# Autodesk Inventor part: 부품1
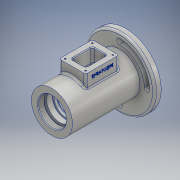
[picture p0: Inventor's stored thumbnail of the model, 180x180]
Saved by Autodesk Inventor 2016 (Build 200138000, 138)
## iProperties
Created: 2017-05
Part Number: 부품1
Material: 알루미늄 6061
Document SubType Name: Modeling
Designer: USER
Density: 2.7 g/cm^3
Appearance: 알루미늄 - 평지
Mass: 676.85 g
Surface Area: 618.164 cm^2
Volume: 250.685 cm^3
Author: USER
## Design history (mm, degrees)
sketch "스케치2"
  geometry: C1 r 53 at (0, 0); 1 further point
  constraints: 1 centre point, 1 coincident
  dimensions: "d0" = 106 diameter of C1
extrude "돌출1" new body sketch "스케치2" distance "d1" = 10; taper "d2" = 0 deg
sketch "스케치3"
  geometry: A1 r 41.5 centre (0, 0) between (0, 41.5) and (-41.5, 0); A2 r 4 centre (0, 41.5) between (0, 37.5) and (0, 45.5); A3 r 4 centre (-41.5, 0) between (-45.5, 0) and (-37.5, 0); A4 r 4 centre (41.5, 0) between (45.5, 0) and (37.5, 0); A5 r 4 centre (0, -41.5) between (0, -37.5) and (0, -45.5); A6 r 37.5 centre (0, 0) between (0, 37.5) and (-37.5, 0); A7 r 37.5 centre (0, 0) between (0, -37.5) and (37.5, 0); A8 r 45.5 centre (0, 0) between (0, 45.5) and (-45.5, 0); A9 r 45.5 centre (0, 0) between (0, -45.5) and (45.5, 0); 1 further point
  constraints: 20 point on circle, 9 centre point, 4 tangent, 3 coincident, 2 horizontal alignment, 2 vertical alignment
  dimensions: "d4" = 83 diameter of A1; "d5" = 8 diameter of A2; "d6" = 8 diameter of A3; "d7" = 8 diameter of A4; "d8" = 8 diameter of A5
extrude "돌출2" cut sketch "스케치3" distance "d9" = 10; taper "d10" = 0 deg
sketch "스케치4"
  geometry: C1 r 31 at (0, 0); 1 further point
  constraints: 1 centre point, 1 coincident
  dimensions: "d11" = 62 diameter of C1
extrude "돌출3" join sketch "스케치4" distance "d12" = 3; taper "d13" = 0 deg
sketch "스케치5"
  geometry: C1 r 31 at (0, 0); 1 further point
  constraints: 1 centre point, 1 coincident
  dimensions: "d14" = 62 diameter of C1
extrude "돌출4" join sketch "스케치5" distance "d15" = 102; taper "d16" = 0 deg
node "작업 평면1"
sketch "스케치6"
  geometry: L1 (37.5, 10)-(37.5, 0) reference; L2 (37.5, 0)-(31, 0) reference; L3 (31, 0)-(31, -102) reference; L4 (31, -102)-(-31, -102) reference; L5 (-31, -102)-(-31, 0) reference; L6 (-31, 0)-(-37.5, 0) reference; L7 (-37.5, 0)-(-37.5, 10) reference; L8 (-37.5, 10)-(-31, 10) reference; L9 (-31, 10)-(-31, 13) reference; L10 (-31, 13)-(31, 13) reference; L11 (31, 13)-(31, 10) reference; L12 (31, 10)-(37.5, 10) reference; L13 (-53, 0)-(-53, 10) reference; L14 (-53, 10)-(-45.5, 10) reference; L15 (-45.5, 10)-(-45.5, 0) reference; L16 (-45.5, 0)-(-53, 0) reference; L17 (53, 10)-(53, 0) reference; L18 (53, 0)-(45.5, 0) reference; L19 (45.5, 0)-(45.5, 10) reference; L20 (45.5, 10)-(53, 10) reference; L21 (0, -102)-(0, 13); L22 (31, 13)-(-31, 13) reference; L23 (21, -102)-(21, -93); L24 (21, -93)-(24, -93); L25 (24, -93)-(24, -90); L26 (24, -90)-(20, -90); L27 (20, -90)-(20, -81); L28 (20, -81)-(17.5, -81); L29 (17.5, -81)-(17.5, -77.75); L30 (17.5, -77.75)-(18.5, -77.75); L31 (18.5, -77.75)-(18.5, -76); L32 (18.5, -76)-(17.5, -76); L33 (17.5, -76)-(17.5, -65); L34 (17.5, -65)-(26, -65); L35 (26, -65)-(26, -27); L36 (26, -27)-(17.5, -27); L37 (17.5, -27)-(17.5, -16); L38 (17.5, -16)-(16.5, -16); L39 (16.5, -16)-(16.5, -11); L40 (16.5, -11)-(10, -11); L41 (10, -11)-(10, -8.3); L42 (10, -8.3)-(12.5, -8.3); L43 (12.5, -8.3)-(12.5, -1); L44 (12.5, -1)-(16, -1); L45 (16, -1)-(22, 13); 1 further point
  constraints: 48 end point, 17 perpendicular, 4 point on line, 2 horizontal, 2 midpoint, 2 vertical
  dimensions: "d18" = 42 diameter of L23 L21; "d19" = 9 distance of L23.start L23.end; "d20" = 48 diameter of L25 L21; "d21" = 40 diameter of L27 L21; "d22" = 3 distance of L24.end L25.end; "d23" = 35 diameter of L29 L21; "d24" = 21 distance between parallel lines of L28 L4; "d25" = 37 diameter of L31 L21; "d26" = 1.75 distance of L30.end L31.end; "d27" = 26 distance between parallel lines of L4 L32; "d28" = 11 distance of L32.end L33.end; "d29" = 35 diameter of L33 L21; "d30" = 52 diameter of L35 L21; "d31" = 38 distance of L34.end L35.end; "d32" = 11 distance of L36.end L37.end; "d33" = 25 diameter of L43 L21; "d34" = 7.3 distance of L42.end L43.end; "d35" = 2.7 distance of L40.end L41.end; "d36" = 20 diameter of L41 L21; "d37" = 5 distance of L38.end L39.end; "d39" = 33 diameter of L39 L21; "d40" = 32 diameter of L44.end L21; "d41" = 44 diameter of L45.end L21
revolve "회전1" sketch "스케치6" stored, may be unused: angle "d42" = 90 deg
feature "스레드1" dims "d43" = 10, "d44" = 0
chamfer "모따기1" distance "d45" = 1; stored, may be unused: second distance "d46" = 2, angle "d47" = 45 deg
chamfer "모따기2" distance "d48" = 1; stored, may be unused: second distance "d49" = 2, angle "d50" = 45 deg
chamfer "모따기3" distance "d51" = 0.7; stored, may be unused: second distance "d52" = 2, angle "d53" = 30 deg
fillet "모깎기1" dims "d54" = 3
fillet "모깎기2" dims "d55" = 3
fillet "모깎기3" dims "d56" = 3
fillet "모깎기4" dims "d57" = 0.3
node "작업 평면2"
sketch "스케치7"
  geometry: L1 (-31, 0)-(-31, -102) reference; L2 (-31, -102)-(31, -102) reference; L3 (31, 0)-(31, -102) reference; L4 (-20, -71)-(20, -71); L5 (20, -71)-(20, -21); L6 (20, -21)-(-20, -21); L7 (-20, -21)-(-20, -71); 3 further points
  constraints: 8 end point, 2 midpoint, 2 parallel, 1 horizontal, 1 perpendicular, 1 vertical alignment
  dimensions: "d59" = 31 distance between parallel lines of L4 L2; "d60" = 40 distance of L4.start L4.end; "d61" = 50 distance of L4.end L5.end
extrude "돌출5" join sketch "스케치7" stored distance "d62" = 102; taper "d63" = 0 deg
sketch "스케치8"
  geometry: L1 (11, 62)-(-11, 62); L2 (-11, 62)-(-11, 30); L3 (-11, 30)-(11, 30); L4 (11, 30)-(11, 62); L5 (20, 71)-(-20, 71) reference; L6 (11, 46)-(-11, 46); L7 (31, 102)-(-31, 102) reference; 3 further points
  constraints: 10 end point, 4 midpoint, 2 parallel, 1 horizontal, 1 perpendicular, 1 vertical alignment
  dimensions: "d64" = 22 distance of L1.start L1.end; "d65" = 32 distance of L1.end L2.end; "d66" = 56 distance between parallel lines of L7 L6
extrude "돌출6" cut sketch "스케치8" stored distance "d67" = 102; taper "d68" = 0 deg
fillet "모깎기5" dims "d69" = 3
fillet "모깎기6" dims "d70" = 3
fillet "모깎기7" dims "d71" = 3
chamfer "모따기4" distance "d72" = 1; stored, may be unused: second distance "d73" = 2, angle "d74" = 30 deg
sketch "스케치9"
  geometry: L1 (15.5, 66.5)-(-15.5, 66.5); L2 (-15.5, 66.5)-(-15.5, 25.5); L3 (-15.5, 25.5)-(15.5, 25.5); L4 (15.5, 25.5)-(15.5, 66.5); L5 (17, 71)-(-17, 71) reference; L6 (15.5, 46)-(-15.5, 46); L7 (31, 102)-(-31, 102) reference; 3 further points
  constraints: 10 end point, 4 midpoint, 2 parallel, 1 horizontal, 1 perpendicular, 1 vertical alignment
  dimensions: "d75" = 31 distance of L1.start L1.end; "d76" = 41 distance of L3.end L1.start; "d77" = 56 distance between parallel lines of L7 L6
hole "구멍1" sketch "스케치9" at (15.5, 66.5), (15.5, 25.5), (-15.5, 25.5), (-15.5, 66.5) diameter "d78" = 2.459; stored, may be unused: countersink angle "d82" = 90 deg, drill point angle "d84" = 118 deg; dims "d79" = 6, "d80" = 4, "d81" = 2, "d83" = 8
fillet "모깎기8" dims "d85" = 3
node "작업 평면3"
sketch "스케치10"
  geometry: L1 (0, 0)-(44, 0) reference; L2 (-34, -13)-(-34, -75) reference; 2 further points
  constraints: 1 other
  dimensions: "d87" = 8 distance from line of L1 point (22, -8); "d88" = 56 distance from line of L2 point (22, -8)
feature "엠보싱1" sketch "스케치10" dims "d89" = 0.5, "d90" = 0
chamfer "모따기5" distance "d91" = 1; stored, may be unused: second distance "d92" = 2, angle "d93" = 30 deg
fillet "모깎기9" dims "d94" = 0.3
fillet "모깎기10" dims "d95" = 0.3
node "솔리드1"
node "절단 모서리 투영1"
other parameters: "d17" = 0, "d58" = 44, "d86" = 0.5
